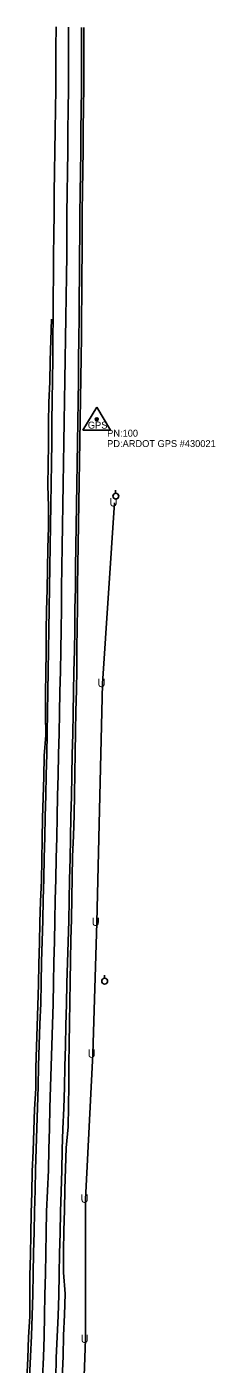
# Model space of a CAD drawing. Extents: x 1383673 to 1386849, y 1973501 to 1978801.
# Drawn here: x 1385195 to 1385331, y 1975362 to 1976326 of the extents above; entities that cross this region are included whole.
import ezdxf

# ---------------------------------------------------------------- set-up
doc = ezdxf.new("R2010")
doc.units = 0
for name, color, linetype in [('56', 7, 'Continuous'), ('B-Super-Deck', 7, 'Continuous'), ('Default', 7, 'Continuous'), ('R_Annotation', 7, 'Continuous'), ('R_Drainage', 7, 'Continuous'), ('S_EDGE_PAVEMENT', 7, 'Continuous'), ('SIGNS', 7, 'Continuous'), ('SIGNS_TX', 7, 'Continuous')]:
    doc.layers.add(name, color=color, linetype=linetype)

msp = doc.modelspace()

# ---------------------------------------------------------------- linework, layer by layer
at = {"layer": '56'}
for p, q in [((1385259.14, 1975990.01), (1385259.14, 1975992.12)), ((1385251.09, 1975640.16), (1385251.09, 1975642.27))]:
    msp.add_line(p, q, dxfattribs=at)
for centre in [(1385259.27, 1975987.87), (1385251.21, 1975638.02)]:
    msp.add_circle(centre, 2.13, dxfattribs=at)
at = {"layer": 'B-Super-Deck'}
msp.add_lwpolyline([(1385206.32, 1975351.82), (1385206.93, 1975366.8), (1385207.53, 1975381.79), (1385207.83, 1975396.79), (1385208.12, 1975411.79), (1385208.42, 1975426.79), (1385208.73, 1975441.78), (1385209, 1975456.78), (1385209.27, 1975471.78), (1385209.91, 1975486.77), (1385210.55, 1975501.75), (1385210.97, 1975516.76), (1385211.38, 1975531.74), (1385211.71, 1975546.74), (1385212.04, 1975561.74), (1385212.52, 1975576.73), (1385213, 1975591.72), (1385213.5, 1975606.71), (1385214, 1975621.71), (1385214, 1975621.71), (1385214.3, 1975636.71), (1385214.59, 1975651.7), (1385214.59, 1975651.7), (1385214.88, 1975666.7), (1385215.17, 1975681.7), (1385215.54, 1975696.7), (1385215.91, 1975711.69), (1385216.29, 1975726.69), (1385216.29, 1975726.69), (1385216.67, 1975741.68), (1385216.97, 1975756.68), (1385217.26, 1975771.68), (1385217.59, 1975786.68), (1385217.59, 1975786.68), (1385217.93, 1975801.67), (1385218.26, 1975816.67), (1385218.59, 1975831.67), (1385218.9, 1975846.67), (1385219.21, 1975861.66), (1385219.45, 1975876.66), (1385219.7, 1975891.66), (1385219.92, 1975906.66), (1385220.15, 1975921.66), (1385220.4, 1975936.66), (1385220.64, 1975951.66), (1385220.87, 1975966.66), (1385221.1, 1975981.65), (1385221.35, 1975996.73), (1385221.6, 1976011.65), (1385221.83, 1976026.65), (1385222.06, 1976041.65), (1385222.29, 1976056.65), (1385222.52, 1976071.65), (1385222.76, 1976086.65), (1385223, 1976101.65), (1385223.23, 1976116.64), (1385223.47, 1976131.64), (1385223.69, 1976146.64), (1385223.69, 1976146.64), (1385223.91, 1976161.64), (1385223.96, 1976176.64), (1385224, 1976191.64), (1385224.15, 1976206.64), (1385224.29, 1976221.64), (1385224.5, 1976236.64), (1385224.7, 1976251.64), (1385224.87, 1976266.64), (1385224.87, 1976266.64), (1385225.04, 1976281.64), (1385225.21, 1976296.64), (1385225.21, 1976311.64), (1385225.1, 1976326.21)], dxfattribs=at)
at = {"layer": 'R_Annotation'}
for p, q in [((1385249.66, 1975852.7), (1385258.3, 1975983.01)), ((1385245.46, 1975680.44), (1385249.66, 1975852.7)), ((1385242.55, 1975585.35), (1385245.46, 1975680.44)), ((1385237.46, 1975480.71), (1385242.55, 1975585.35)), ((1385237.49, 1975379.69), (1385237.46, 1975480.71)), ((1385234.33, 1975297.48), (1385237.49, 1975379.69))]:
    msp.add_line(p, q, dxfattribs=at)
at = {"layer": 'R_Drainage'}
for points in [[(1385220.61, 1975351.43), (1385221.16, 1975367.42), (1385221.42, 1975382.43), (1385222.24, 1975397.41), (1385222.7, 1975412.41), (1385221.53, 1975427.91), (1385221.44, 1975442.91), (1385221.75, 1975457.91), (1385222.19, 1975472.91), (1385222.53, 1975487.9), (1385222.98, 1975502.9), (1385223.31, 1975517.9), (1385224.79, 1975532.87), (1385225.08, 1975547.87), (1385225.38, 1975562.87), (1385225.39, 1975577.87), (1385225.49, 1975592.87), (1385225.78, 1975607.87), (1385225.99, 1975622.87), (1385226.27, 1975637.87), (1385226.59, 1975652.86), (1385226.89, 1975667.86), (1385227.18, 1975682.86), (1385227.47, 1975697.86), (1385227.72, 1975712.86), (1385228.01, 1975727.85), (1385228.69, 1975742.85), (1385229.21, 1975757.84), (1385229.49, 1975772.84), (1385229.64, 1975787.84), (1385229.93, 1975802.84), (1385230.19, 1975817.83), (1385230.48, 1975832.83), (1385230.78, 1975847.83), (1385231.04, 1975862.83), (1385231.1, 1975877.88), (1385231.27, 1975892.88), (1385231.5, 1975907.88), (1385231.67, 1975922.88), (1385231.86, 1975937.88), (1385232.08, 1975952.88), (1385232.28, 1975967.88), (1385232.51, 1975982.88), (1385232.74, 1975997.88), (1385232.97, 1976012.87), (1385233.27, 1976027.87), (1385233.53, 1976042.87), (1385233.79, 1976057.87), (1385234.02, 1976072.87), (1385234.25, 1976087.87), (1385234.48, 1976102.87), (1385234.6, 1976117.87), (1385234.69, 1976132.87), (1385234.79, 1976147.87), (1385234.88, 1976162.88), (1385234.9, 1976177.89), (1385235.06, 1976192.89), (1385235.27, 1976207.88), (1385235.46, 1976222.88), (1385235.62, 1976237.88), (1385235.76, 1976252.88), (1385235.96, 1976267.88), (1385236.05, 1976282.89), (1385236.26, 1976297.88), (1385236.05, 1976326.05)], [(1385194.92, 1975351.15), (1385195.81, 1975366.13), (1385196.29, 1975381.13), (1385197.18, 1975396.1), (1385197.26, 1975411.12), (1385197.24, 1975425.64), (1385197.59, 1975440.64), (1385197.91, 1975455.63), (1385198.2, 1975470.63), (1385198.52, 1975485.63), (1385198.79, 1975500.63), (1385199.49, 1975515.62), (1385200.09, 1975530.61), (1385200.45, 1975545.61), (1385201.5, 1975560.59), (1385201.6, 1975575.59), (1385201.9, 1975590.59), (1385202.39, 1975605.58), (1385202.87, 1975620.58), (1385203.44, 1975635.57), (1385203.78, 1975650.57), (1385204.07, 1975665.56), (1385204.36, 1975680.56), (1385204.76, 1975695.56), (1385205.52, 1975710.55), (1385205.81, 1975725.54), (1385206.1, 1975740.54), (1385206.36, 1975755.54), (1385206.8, 1975770.54), (1385207.17, 1975785.53), (1385207.63, 1975800.53), (1385208.83, 1975815.51), (1385208.5, 1975830.52), (1385208.46, 1975845.52), (1385208.75, 1975860.52), (1385208.85, 1975875.48), (1385209.02, 1975890.48), (1385209.25, 1975905.48), (1385209.59, 1975920.48), (1385209.93, 1975935.47), (1385210.27, 1975950.47), (1385210.66, 1975965.47), (1385210.63, 1975980.47), (1385210.26, 1975995.48), (1385210.5, 1976010.48), (1385210.69, 1976025.48), (1385210.73, 1976040.48), (1385210.96, 1976055.48), (1385211.73, 1976070.47), (1385211.96, 1976085.47), (1385212.41, 1976100.46), (1385212.9, 1976115.46)]]:
    msp.add_lwpolyline(points, dxfattribs=at)
at = {"layer": 'S_EDGE_PAVEMENT'}
for points in [[(1385197, 1975352.23), (1385197.71, 1975367.18), (1385198.44, 1975382.16), (1385198.83, 1975396.96), (1385199.22, 1975411.96), (1385199.55, 1975426.97), (1385199.88, 1975441.96), (1385200.18, 1975456.94), (1385200.49, 1975471.94), (1385200.93, 1975487.15), (1385201.36, 1975502.15), (1385201.85, 1975517), (1385202.34, 1975531.99), (1385202.76, 1975546.94), (1385203.18, 1975561.93), (1385203.54, 1975577.02), (1385203.91, 1975592.02), (1385204.46, 1975607.02), (1385205.01, 1975622.01), (1385205.36, 1975636.88), (1385205.71, 1975651.87), (1385206.08, 1975666.87), (1385206.46, 1975681.87), (1385206.86, 1975696.91), (1385207.25, 1975711.91), (1385207.58, 1975726.91), (1385207.92, 1975741.91), (1385208.26, 1975756.85), (1385208.61, 1975771.85), (1385209, 1975786.87), (1385209.39, 1975801.86), (1385209.66, 1975816.86), (1385209.92, 1975831.86), (1385210.21, 1975846.85), (1385210.51, 1975861.84), (1385210.73, 1975876.8), (1385210.96, 1975891.8), (1385211.17, 1975906.79), (1385211.38, 1975921.79), (1385211.62, 1975936.8), (1385211.86, 1975951.8), (1385212.08, 1975966.79), (1385212.3, 1975981.79), (1385212.56, 1975996.88), (1385212.82, 1976011.8), (1385212.99, 1976026.79), (1385213.16, 1976041.79), (1385213.34, 1976056.79), (1385213.52, 1976071.79), (1385213.71, 1976086.79), (1385213.89, 1976101.79), (1385213.99, 1976116.79), (1385214.08, 1976131.79), (1385214.23, 1976146.78), (1385214.37, 1976161.78), (1385214.52, 1976176.67), (1385214.67, 1976191.67), (1385214.84, 1976206.74), (1385215.01, 1976221.74), (1385215.24, 1976236.77), (1385215.46, 1976251.77), (1385215.66, 1976266.75), (1385215.85, 1976281.75), (1385215.94, 1976296.75), (1385216.01, 1976311.57), (1385216.08, 1976326.49)], [(1385215.88, 1975351.4), (1385216.25, 1975366.43), (1385216.96, 1975381.41), (1385217.6, 1975396.6), (1385218.06, 1975411.6), (1385218.35, 1975426.58), (1385218.71, 1975441.58), (1385219.01, 1975456.6), (1385219.31, 1975471.6), (1385219.68, 1975486.35), (1385220.16, 1975501.34), (1385220.61, 1975516.5), (1385220.61, 1975516.5), (1385221.1, 1975531.48), (1385221.69, 1975546.52), (1385222.11, 1975561.51), (1385222.47, 1975576.41), (1385222.82, 1975591.4), (1385223.16, 1975606.39), (1385223.55, 1975621.39), (1385224, 1975636.52), (1385224.49, 1975651.51), (1385224.92, 1975666.51), (1385225.28, 1975681.5), (1385225.58, 1975696.45), (1385225.91, 1975711.44), (1385226.23, 1975726.44), (1385226.53, 1975741.43), (1385226.89, 1975756.49), (1385227.23, 1975771.49), (1385227.53, 1975786.45), (1385227.83, 1975801.45), (1385228.15, 1975816.45), (1385228.48, 1975831.45), (1385228.77, 1975846.46), (1385229.06, 1975861.46), (1385229.33, 1975876.5), (1385229.56, 1975891.5), (1385229.78, 1975906.51), (1385230.03, 1975921.51), (1385230.27, 1975936.5), (1385230.5, 1975951.5), (1385230.72, 1975966.51), (1385230.95, 1975981.5), (1385231.18, 1975996.57), (1385231.41, 1976011.49), (1385231.64, 1976026.5), (1385231.88, 1976041.5), (1385232.12, 1976056.5), (1385232.27, 1976071.5), (1385232.4, 1976086.49), (1385232.57, 1976101.49), (1385232.71, 1976116.5), (1385232.83, 1976131.5), (1385232.97, 1976146.51), (1385233.09, 1976161.51), (1385233.22, 1976176.62), (1385233.39, 1976191.62), (1385233.58, 1976206.55), (1385233.79, 1976221.55), (1385233.94, 1976236.52), (1385234.06, 1976251.52), (1385234.2, 1976266.53), (1385234.39, 1976281.53), (1385234.58, 1976296.54), (1385234.57, 1976311.71), (1385234.53, 1976325.99)]]:
    msp.add_lwpolyline(points, dxfattribs=at)
at = {"layer": 'SIGNS'}
for p, q in [((1385245.51, 1976052), (1385235.48, 1976035.49)), ((1385245.51, 1976052), (1385255.33, 1976035.49)), ((1385235.48, 1976035.49), (1385255.33, 1976035.49))]:
    msp.add_line(p, q, dxfattribs=at)
for radius in [1.04, 0.609, 0.344]:
    msp.add_circle((1385245.51, 1976043.3), radius, dxfattribs=at)

# ---------------------------------------------------------------- texts
at = {"layer": 'Default'}
for p in [(1385254.67, 1975980.46), (1385246.03, 1975850.15), (1385241.83, 1975677.9), (1385238.92, 1975582.81), (1385233.83, 1975478.16), (1385233.87, 1975377.14)]:
    msp.add_text('U', height=6, dxfattribs=at).set_placement(p)
at = {"layer": 'SIGNS'}
msp.add_text('GPS', height=5, dxfattribs=at).set_placement((1385239.07, 1976036.6))
at = {"layer": 'SIGNS_TX'}
for s, p in [('PN:100', (1385253.01, 1976030.8)), ('PD:ARDOT GPS #430021', (1385253.01, 1976023.3))]:
    msp.add_text(s, height=5, dxfattribs=at).set_placement(p)

doc.saveas('drawing.dxf')
